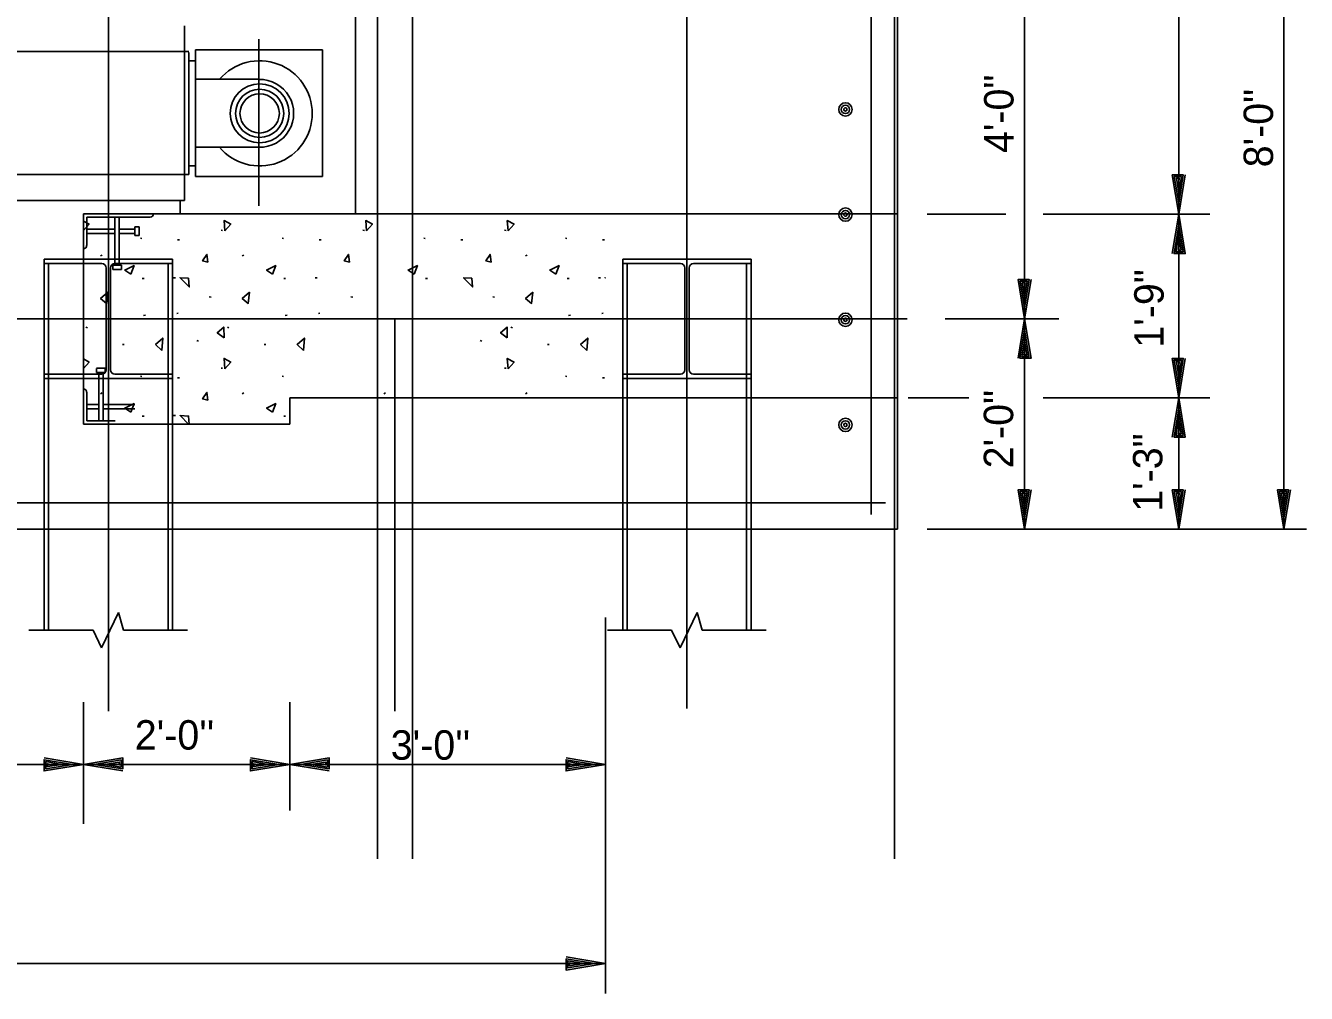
# Model space of a CAD drawing. Extents: x -11983 to -11903, y -13969.5 to -13913.5.
# Drawn here: x -11943.67 to -11931.5, y -13933.48 to -13924.28 of the extents above; entities that cross this region are included whole.
import ezdxf

# ---------------------------------------------------------------- set-up
doc = ezdxf.new("R2010")
doc.units = 0
for name, color, linetype in [('Level 1', 7, 'Continuous'), ('Level 2', 7, 'Continuous'), ('Level 22', 7, 'Continuous'), ('Level 25', 7, 'Continuous'), ('Level 3', 7, 'Continuous'), ('Level 44', 7, 'Continuous'), ('Level 50', 7, 'Continuous'), ('Level 6', 7, 'Continuous')]:
    doc.layers.add(name, color=color, linetype=linetype)

msp = doc.modelspace()

# ---------------------------------------------------------------- linework, layer by layer
at = {"layer": 'Level 1'}
msp.add_line((-11932.713, -13926.07), (-11932.713, -13927.816), dxfattribs=at)
at = {"layer": 'Level 2'}
for p, q in [((-11940.33, -13917.157), (-11940.33, -13932.202)), ((-11939.997, -13917.157), (-11939.997, -13932.202)), ((-11935.413, -13917.157), (-11935.413, -13932.202)), ((-11935.387, -13921.074), (-11935.387, -13927.066)), ((-11935.387, -13921.074), (-11935.387, -13929.066)), ((-11942.163, -13924.279), (-11942.163, -13925.941)), ((-11942.059, -13925.713), (-11942.059, -13924.506)), ((-11940.852, -13924.506), (-11942.059, -13924.506)), ((-11940.852, -13925.713), (-11940.852, -13924.506)), ((-11968.183, -13924.524), (-11942.122, -13924.524)), ((-11942.163, -13924.532), (-11942.163, -13925.698)), ((-11942.122, -13924.532), (-11942.122, -13925.691)), ((-11942.059, -13924.61), (-11942.122, -13924.61)), ((-11941.456, -13924.787), (-11942.059, -13924.787)), ((-11941.456, -13925.432), (-11942.059, -13925.432)), ((-11968.183, -13925.691), (-11942.122, -13925.691)), ((-11942.059, -13925.609), (-11942.122, -13925.609)), ((-11940.852, -13925.713), (-11942.059, -13925.713)), ((-11968.183, -13925.941), (-11942.163, -13925.941)), ((-11942.458, -13926.066), (-11943.125, -13926.066)), ((-11943.125, -13926.066), (-11943.125, -13926.399)), ((-11943.125, -13926.066), (-11943.125, -13928.066)), ((-11935.387, -13926.066), (-11943.125, -13926.066)), ((-11942.364, -13926.066), (-11943.125, -13926.066)), ((-11942.792, -13926.066), (-11942.792, -13926.066)), ((-11942.489, -13926.097), (-11943.093, -13926.097)), ((-11943.093, -13926.368), (-11943.093, -13926.097)), ((-11942.825, -13926.212), (-11943.093, -13926.212)), ((-11942.825, -13926.555), (-11942.825, -13926.097)), ((-11942.784, -13926.555), (-11942.784, -13926.097)), ((-11942.635, -13926.212), (-11942.784, -13926.212)), ((-11942.635, -13926.274), (-11942.635, -13926.191)), ((-11942.594, -13926.191), (-11942.635, -13926.191)), ((-11942.594, -13926.274), (-11942.594, -13926.191)), ((-11942.825, -13926.253), (-11943.093, -13926.253)), ((-11942.635, -13926.253), (-11942.784, -13926.253)), ((-11942.594, -13926.274), (-11942.635, -13926.274)), ((-11943.125, -13926.399), (-11943.125, -13926.399)), ((-11943.125, -13926.399), (-11943.125, -13927.733)), ((-11942.278, -13926.498), (-11943.497, -13926.498)), ((-11943.497, -13926.498), (-11943.497, -13926.54)), ((-11943.497, -13926.54), (-11943.497, -13928.566)), ((-11942.95, -13926.54), (-11943.497, -13926.54)), ((-11943.455, -13926.54), (-11943.455, -13928.566)), ((-11942.763, -13926.555), (-11942.846, -13926.555)), ((-11942.846, -13926.595), (-11942.846, -13926.555)), ((-11942.278, -13926.54), (-11942.825, -13926.54)), ((-11942.763, -13926.595), (-11942.763, -13926.555)), ((-11942.32, -13926.54), (-11942.32, -13928.566)), ((-11942.278, -13926.498), (-11942.278, -13926.54)), ((-11942.278, -13926.54), (-11942.278, -13928.566)), ((-11936.778, -13926.498), (-11937.997, -13926.498)), ((-11937.997, -13926.498), (-11937.997, -13926.54)), ((-11937.997, -13926.54), (-11937.997, -13928.566)), ((-11937.45, -13926.54), (-11937.997, -13926.54)), ((-11937.955, -13926.54), (-11937.955, -13928.566)), ((-11936.778, -13926.54), (-11937.325, -13926.54)), ((-11936.82, -13926.54), (-11936.82, -13928.566)), ((-11936.778, -13926.498), (-11936.778, -13926.54)), ((-11936.778, -13926.54), (-11936.778, -13928.566)), ((-11942.908, -13926.582), (-11942.908, -13927.55)), ((-11942.867, -13926.582), (-11942.867, -13927.55)), ((-11942.763, -13926.597), (-11942.846, -13926.597)), ((-11937.408, -13926.582), (-11937.408, -13927.55)), ((-11937.367, -13926.582), (-11937.367, -13927.55)), ((-11935.387, -13927.066), (-11935.387, -13929.066)), ((-11942.917, -13927.535), (-11943, -13927.535)), ((-11943, -13927.537), (-11943, -13927.577)), ((-11942.917, -13927.537), (-11942.917, -13927.577)), ((-11942.95, -13927.592), (-11943.497, -13927.592)), ((-11943.497, -13927.592), (-11943.497, -13927.634)), ((-11942.278, -13927.634), (-11943.497, -13927.634)), ((-11942.917, -13927.577), (-11943, -13927.577)), ((-11942.979, -13927.577), (-11942.979, -13928.035)), ((-11942.937, -13927.577), (-11942.937, -13928.035)), ((-11942.278, -13927.592), (-11942.825, -13927.592)), ((-11942.278, -13927.592), (-11942.278, -13927.634)), ((-11937.45, -13927.592), (-11937.997, -13927.592)), ((-11937.997, -13927.592), (-11937.997, -13927.634)), ((-11936.778, -13927.634), (-11937.997, -13927.634)), ((-11936.778, -13927.592), (-11937.325, -13927.592)), ((-11936.778, -13927.592), (-11936.778, -13927.634)), ((-11943.125, -13927.733), (-11943.125, -13927.733)), ((-11943.125, -13927.733), (-11943.125, -13928.066)), ((-11943.093, -13927.764), (-11943.093, -13928.035)), ((-11942.979, -13927.879), (-11943.093, -13927.879)), ((-11942.635, -13927.879), (-11942.937, -13927.879)), ((-11941.163, -13927.816), (-11941.163, -13928.066)), ((-11935.387, -13927.816), (-11941.163, -13927.816)), ((-11942.979, -13927.92), (-11943.093, -13927.92)), ((-11942.823, -13928.035), (-11943.093, -13928.035)), ((-11942.635, -13927.92), (-11942.937, -13927.92)), ((-11941.163, -13928.066), (-11943.125, -13928.066)), ((-11943.497, -13930.027), (-11943.497, -13928.566)), ((-11943.455, -13930.027), (-11943.455, -13928.566)), ((-11942.32, -13930.027), (-11942.32, -13928.566)), ((-11942.278, -13930.027), (-11942.278, -13928.566)), ((-11937.997, -13930.027), (-11937.997, -13928.566)), ((-11937.955, -13930.027), (-11937.955, -13928.566)), ((-11936.82, -13930.027), (-11936.82, -13928.566)), ((-11936.778, -13930.027), (-11936.778, -13928.566)), ((-11935.387, -13929.066), (-11957.178, -13929.066)), ((-11936.387, -13929.066), (-11936.662, -13929.066)), ((-11942.79, -13929.857), (-11942.953, -13930.194)), ((-11942.742, -13930.027), (-11942.79, -13929.857)), ((-11937.29, -13929.857), (-11937.453, -13930.194)), ((-11937.242, -13930.027), (-11937.29, -13929.857)), ((-11943.033, -13930.027), (-11943.643, -13930.027)), ((-11942.953, -13930.194), (-11943.033, -13930.027)), ((-11942.134, -13930.027), (-11942.742, -13930.027)), ((-11937.533, -13930.027), (-11938.143, -13930.027)), ((-11937.453, -13930.194), (-11937.533, -13930.027)), ((-11936.634, -13930.027), (-11937.242, -13930.027))]:
    msp.add_line(p, q, dxfattribs=at)
for radius in [0.281, 0.229, 0.187]:
    msp.add_circle((-11941.449, -13925.111), radius, dxfattribs=at)
for centre, radius, start, end in [((-11941.449, -13925.111), 0.5, 220.0641, 139.6289), ((-11941.449, -13925.111), 0.323, 268.7527, 91.2396), ((-11942.489, -13926.066), 0.0312, 270, 0), ((-11943.125, -13926.368), 0.0312, 270, 0), ((-11942.95, -13926.582), 0.0417, 0, 90), ((-11942.825, -13926.582), 0.0417, 90, 180), ((-11937.45, -13926.582), 0.0417, 0, 90), ((-11937.325, -13926.582), 0.0417, 90, 180), ((-11942.95, -13927.55), 0.0417, 270, 0), ((-11942.825, -13927.55), 0.0417, 180, 270), ((-11937.45, -13927.55), 0.0417, 270, 0), ((-11937.325, -13927.55), 0.0417, 180, 270), ((-11943.125, -13927.764), 0.0312, 0, 90)]:
    msp.add_arc(centre, radius, start, end, dxfattribs=at)
at = {"layer": 'Level 22'}
for p, q in [((-11942.887, -13924.649), (-11942.887, -13923.074)), ((-11937.387, -13924.649), (-11937.387, -13923.074)), ((-11942.887, -13924.649), (-11942.887, -13927.066)), ((-11942.887, -13924.649), (-11942.887, -13927.066)), ((-11937.387, -13924.649), (-11937.387, -13927.066)), ((-11942.887, -13927.066), (-11942.887, -13927.857)), ((-11937.387, -13927.066), (-11937.387, -13927.857)), ((-11943.125, -13930.71), (-11943.125, -13931.868)), ((-11941.163, -13930.71), (-11941.163, -13931.742)), ((-11938.163, -13931.302), (-11938.163, -13930.71)), ((-11941.163, -13931.302), (-11943.125, -13931.302)), ((-11938.163, -13931.302), (-11941.163, -13931.302))]:
    msp.add_line(p, q, dxfattribs=at)
at = {"layer": 'Level 25'}
for p, q in [((-11940.538, -13926.066), (-11940.538, -13923.849)), ((-11942.205, -13926.066), (-11942.205, -13925.941))]:
    msp.add_line(p, q, dxfattribs=at)
at = {"layer": 'Level 3'}
for p, q in [((-11932.713, -13921.074), (-11932.713, -13926.07)), ((-11931.713, -13921.074), (-11931.713, -13929.066)), ((-11934.178, -13923.074), (-11934.178, -13927.066)), ((-11932.713, -13925.966), (-11932.713, -13925.966)), ((-11934.355, -13926.07), (-11935.104, -13926.07)), ((-11932.418, -13926.07), (-11934.002, -13926.07)), ((-11932.713, -13926.07), (-11932.713, -13926.07)), ((-11935.294, -13927.066), (-11955.163, -13927.066)), ((-11942.887, -13927.066), (-11942.887, -13930.796)), ((-11942.887, -13927.066), (-11942.887, -13930.77)), ((-11940.163, -13927.066), (-11940.163, -13930.796)), ((-11940.163, -13927.066), (-11940.163, -13930.796)), ((-11937.387, -13927.066), (-11937.387, -13930.77)), ((-11933.851, -13927.066), (-11934.934, -13927.066)), ((-11934.178, -13927.066), (-11934.178, -13929.066)), ((-11934.707, -13927.816), (-11935.286, -13927.816)), ((-11932.418, -13927.816), (-11934.002, -13927.816)), ((-11932.713, -13927.816), (-11932.713, -13929.066)), ((-11931.713, -13928.962), (-11931.713, -13928.962)), ((-11931.499, -13929.066), (-11935.104, -13929.066)), ((-11931.713, -13929.066), (-11931.713, -13929.066)), ((-11938.163, -13929.904), (-11938.163, -13932.694)), ((-11938.163, -13930.824), (-11938.163, -13933.48)), ((-11967.163, -13931.302), (-11943.125, -13931.302)), ((-11938.163, -13933.196), (-11972.163, -13933.196))]:
    msp.add_line(p, q, dxfattribs=at)
for points in [[(-11932.651, -13925.696), (-11932.713, -13926.07), (-11932.775, -13925.696), (-11932.669, -13925.696), (-11932.713, -13925.966), (-11932.755, -13925.712), (-11932.687, -13925.712), (-11932.713, -13925.866), (-11932.735, -13925.728), (-11932.707, -13925.728), (-11932.713, -13925.762)], [(-11931.651, -13928.692), (-11931.713, -13929.066), (-11931.775, -13928.692), (-11931.669, -13928.692), (-11931.713, -13928.962), (-11931.755, -13928.708), (-11931.687, -13928.708), (-11931.713, -13928.862), (-11931.735, -13928.724), (-11931.707, -13928.724), (-11931.713, -13928.758)]]:
    msp.add_lwpolyline(points, dxfattribs=at)
at = {"layer": 'Level 44'}
for p, q in [((-11942.57, -13926.302), (-11942.583, -13926.299)), ((-11942.211, -13926.313), (-11942.229, -13926.313)), ((-11941.801, -13926.224), (-11941.814, -13926.223)), ((-11941.223, -13926.302), (-11941.236, -13926.299)), ((-11940.864, -13926.313), (-11940.882, -13926.313)), ((-11940.454, -13926.224), (-11940.467, -13926.223)), ((-11939.876, -13926.302), (-11939.89, -13926.299)), ((-11939.518, -13926.313), (-11939.536, -13926.313)), ((-11939.107, -13926.224), (-11939.121, -13926.223)), ((-11938.53, -13926.302), (-11938.543, -13926.299)), ((-11938.171, -13926.313), (-11938.189, -13926.313)), ((-11942.947, -13926.459), (-11942.963, -13926.467)), ((-11941.6, -13926.459), (-11941.616, -13926.467)), ((-11938.907, -13926.459), (-11938.923, -13926.467)), ((-11942.548, -13926.68), (-11942.566, -13926.68)), ((-11942.25, -13926.674), (-11942.267, -13926.674)), ((-11941.202, -13926.68), (-11941.22, -13926.68)), ((-11940.903, -13926.674), (-11940.92, -13926.674)), ((-11939.855, -13926.68), (-11939.873, -13926.68)), ((-11938.508, -13926.68), (-11938.526, -13926.68)), ((-11938.21, -13926.674), (-11938.227, -13926.674)), ((-11941.91, -13926.86), (-11941.928, -13926.857)), ((-11940.564, -13926.86), (-11940.581, -13926.857)), ((-11939.217, -13926.86), (-11939.234, -13926.857)), ((-11942.534, -13927.029), (-11942.552, -13927.034)), ((-11942.223, -13927.011), (-11942.236, -13927.016)), ((-11941.187, -13927.029), (-11941.205, -13927.034)), ((-11940.877, -13927.011), (-11940.89, -13927.016)), ((-11938.494, -13927.029), (-11938.512, -13927.034)), ((-11938.183, -13927.011), (-11938.196, -13927.016)), ((-11943.087, -13927.152), (-11943.102, -13927.143)), ((-11941.741, -13927.152), (-11941.756, -13927.143)), ((-11939.047, -13927.152), (-11939.062, -13927.143)), ((-11942.738, -13927.308), (-11942.753, -13927.31)), ((-11942.031, -13927.276), (-11942.045, -13927.27)), ((-11941.391, -13927.308), (-11941.406, -13927.31)), ((-11939.338, -13927.276), (-11939.352, -13927.27)), ((-11938.698, -13927.308), (-11938.713, -13927.31)), ((-11941.801, -13927.535), (-11941.814, -13927.534)), ((-11939.107, -13927.535), (-11939.121, -13927.534)), ((-11942.57, -13927.613), (-11942.583, -13927.611)), ((-11942.211, -13927.625), (-11942.229, -13927.625)), ((-11941.223, -13927.613), (-11941.236, -13927.611)), ((-11938.53, -13927.613), (-11938.543, -13927.611)), ((-11938.171, -13927.625), (-11938.189, -13927.625)), ((-11942.947, -13927.77), (-11942.963, -13927.778)), ((-11941.6, -13927.77), (-11941.616, -13927.778)), ((-11940.254, -13927.77), (-11940.27, -13927.778)), ((-11938.907, -13927.77), (-11938.923, -13927.778)), ((-11942.548, -13927.992), (-11942.566, -13927.992)), ((-11942.25, -13927.985), (-11942.267, -13927.985)), ((-11941.202, -13927.992), (-11941.22, -13927.992))]:
    msp.add_line(p, q, dxfattribs=at)
for points in [[(-11943.125, -13926.225), (-11943.071, -13926.164), (-11943.125, -13926.136)], [(-11938.163, -13926.674), (-11938.165, -13926.674), (-11938.163, -13926.675)], [(-11943.125, -13927.537), (-11943.071, -13927.476), (-11943.125, -13927.447)], [(-11942.119, -13928.066), (-11942.125, -13927.99), (-11942.205, -13927.985), (-11942.126, -13928.066)]]:
    msp.add_lwpolyline(points, dxfattribs=at)
for points in [[(-11941.781, -13926.228), (-11941.724, -13926.164), (-11941.788, -13926.13)], [(-11940.435, -13926.228), (-11940.378, -13926.164), (-11940.441, -13926.13)], [(-11939.088, -13926.228), (-11939.031, -13926.164), (-11939.095, -13926.13)], [(-11941.942, -13926.526), (-11941.951, -13926.453), (-11941.992, -13926.514)], [(-11940.595, -13926.526), (-11940.604, -13926.453), (-11940.645, -13926.514)], [(-11939.248, -13926.526), (-11939.258, -13926.453), (-11939.299, -13926.514)], [(-11942.674, -13926.641), (-11942.643, -13926.559), (-11942.731, -13926.602)], [(-11941.328, -13926.641), (-11941.296, -13926.559), (-11941.384, -13926.602)], [(-11939.981, -13926.641), (-11939.949, -13926.559), (-11940.038, -13926.602)], [(-11938.634, -13926.641), (-11938.603, -13926.559), (-11938.691, -13926.602)], [(-11942.125, -13926.678), (-11942.205, -13926.674), (-11942.118, -13926.762)], [(-11939.431, -13926.678), (-11939.511, -13926.674), (-11939.425, -13926.762)], [(-11942.893, -13926.812), (-11942.961, -13926.872), (-11942.905, -13926.919)], [(-11941.546, -13926.812), (-11941.615, -13926.872), (-11941.558, -13926.919)], [(-11938.853, -13926.812), (-11938.921, -13926.872), (-11938.865, -13926.919)], [(-11941.788, -13927.247), (-11941.852, -13927.198), (-11941.791, -13927.144)], [(-11939.095, -13927.247), (-11939.159, -13927.198), (-11939.097, -13927.144)], [(-11942.378, -13927.367), (-11942.439, -13927.31), (-11942.371, -13927.249)], [(-11941.031, -13927.367), (-11941.093, -13927.31), (-11941.024, -13927.249)], [(-11938.338, -13927.367), (-11938.399, -13927.31), (-11938.331, -13927.249)], [(-11941.781, -13927.54), (-11941.724, -13927.476), (-11941.788, -13927.442)], [(-11939.088, -13927.54), (-11939.031, -13927.476), (-11939.095, -13927.442)], [(-11941.942, -13927.838), (-11941.951, -13927.765), (-11941.992, -13927.826)], [(-11942.674, -13927.953), (-11942.643, -13927.871), (-11942.731, -13927.914)], [(-11941.328, -13927.953), (-11941.296, -13927.871), (-11941.384, -13927.914)]]:
    msp.add_lwpolyline(points, close=True, dxfattribs=at)
at = {"layer": 'Level 50'}
for p, q in [((-11941.456, -13924.407), (-11941.456, -13925.991)), ((-11932.713, -13926.07), (-11932.713, -13926.07)), ((-11932.713, -13926.174), (-11932.713, -13926.174)), ((-11934.178, -13926.962), (-11934.178, -13926.962)), ((-11934.178, -13927.066), (-11934.178, -13927.066)), ((-11934.178, -13927.066), (-11934.178, -13927.066)), ((-11934.178, -13927.17), (-11934.178, -13927.17)), ((-11932.713, -13927.712), (-11932.713, -13927.712)), ((-11932.713, -13927.816), (-11932.713, -13927.816)), ((-11932.713, -13927.816), (-11932.713, -13927.816)), ((-11932.713, -13927.92), (-11932.713, -13927.92)), ((-11943.125, -13928.066), (-11942.792, -13928.066)), ((-11934.178, -13928.962), (-11934.178, -13928.962)), ((-11932.713, -13928.962), (-11932.713, -13928.962)), ((-11934.178, -13929.066), (-11934.178, -13929.066)), ((-11932.713, -13929.066), (-11932.713, -13929.066)), ((-11943.229, -13931.302), (-11943.229, -13931.302)), ((-11943.125, -13931.302), (-11943.125, -13931.302)), ((-11943.125, -13931.302), (-11943.125, -13931.302)), ((-11943.021, -13931.302), (-11943.021, -13931.302)), ((-11941.267, -13931.302), (-11941.267, -13931.302)), ((-11941.163, -13931.302), (-11941.163, -13931.302)), ((-11941.163, -13931.302), (-11941.163, -13931.302)), ((-11941.059, -13931.302), (-11941.059, -13931.302)), ((-11938.267, -13931.302), (-11938.267, -13931.302)), ((-11938.163, -13931.302), (-11938.163, -13931.302)), ((-11938.267, -13933.196), (-11938.267, -13933.196)), ((-11938.163, -13933.196), (-11938.163, -13933.196))]:
    msp.add_line(p, q, dxfattribs=at)
for points in [[(-11932.775, -13926.444), (-11932.713, -13926.07), (-11932.651, -13926.444), (-11932.757, -13926.444), (-11932.713, -13926.174), (-11932.671, -13926.428), (-11932.739, -13926.428), (-11932.713, -13926.274), (-11932.691, -13926.412), (-11932.719, -13926.412), (-11932.713, -13926.378)], [(-11934.116, -13926.692), (-11934.178, -13927.066), (-11934.24, -13926.692), (-11934.134, -13926.692), (-11934.178, -13926.962), (-11934.22, -13926.708), (-11934.152, -13926.708), (-11934.178, -13926.862), (-11934.2, -13926.724), (-11934.172, -13926.724), (-11934.178, -13926.758)], [(-11934.24, -13927.44), (-11934.178, -13927.066), (-11934.116, -13927.44), (-11934.222, -13927.44), (-11934.178, -13927.17), (-11934.136, -13927.424), (-11934.204, -13927.424), (-11934.178, -13927.27), (-11934.156, -13927.408), (-11934.184, -13927.408), (-11934.178, -13927.374)], [(-11932.651, -13927.442), (-11932.713, -13927.816), (-11932.775, -13927.442), (-11932.669, -13927.442), (-11932.713, -13927.712), (-11932.755, -13927.458), (-11932.687, -13927.458), (-11932.713, -13927.612), (-11932.735, -13927.474), (-11932.707, -13927.474), (-11932.713, -13927.508)], [(-11932.775, -13928.19), (-11932.713, -13927.816), (-11932.651, -13928.19), (-11932.757, -13928.19), (-11932.713, -13927.92), (-11932.671, -13928.174), (-11932.739, -13928.174), (-11932.713, -13928.02), (-11932.691, -13928.158), (-11932.719, -13928.158), (-11932.713, -13928.124)], [(-11934.116, -13928.692), (-11934.178, -13929.066), (-11934.24, -13928.692), (-11934.134, -13928.692), (-11934.178, -13928.962), (-11934.22, -13928.708), (-11934.152, -13928.708), (-11934.178, -13928.862), (-11934.2, -13928.724), (-11934.172, -13928.724), (-11934.178, -13928.758)], [(-11932.651, -13928.692), (-11932.713, -13929.066), (-11932.775, -13928.692), (-11932.669, -13928.692), (-11932.713, -13928.962), (-11932.755, -13928.708), (-11932.687, -13928.708), (-11932.713, -13928.862), (-11932.735, -13928.724), (-11932.707, -13928.724), (-11932.713, -13928.758)], [(-11943.499, -13931.24), (-11943.125, -13931.302), (-11943.499, -13931.364), (-11943.499, -13931.258), (-11943.229, -13931.302), (-11943.483, -13931.344), (-11943.483, -13931.276), (-11943.329, -13931.302), (-11943.467, -13931.324), (-11943.467, -13931.296), (-11943.433, -13931.302)], [(-11942.751, -13931.364), (-11943.125, -13931.302), (-11942.751, -13931.24), (-11942.751, -13931.346), (-11943.021, -13931.302), (-11942.767, -13931.26), (-11942.767, -13931.328), (-11942.921, -13931.302), (-11942.783, -13931.28), (-11942.783, -13931.308), (-11942.817, -13931.302)], [(-11941.537, -13931.24), (-11941.163, -13931.302), (-11941.537, -13931.364), (-11941.537, -13931.258), (-11941.267, -13931.302), (-11941.521, -13931.344), (-11941.521, -13931.276), (-11941.367, -13931.302), (-11941.505, -13931.324), (-11941.505, -13931.296), (-11941.471, -13931.302)], [(-11940.789, -13931.364), (-11941.163, -13931.302), (-11940.789, -13931.24), (-11940.789, -13931.346), (-11941.059, -13931.302), (-11940.805, -13931.26), (-11940.805, -13931.328), (-11940.959, -13931.302), (-11940.821, -13931.28), (-11940.821, -13931.308), (-11940.855, -13931.302)], [(-11938.537, -13931.24), (-11938.163, -13931.302), (-11938.537, -13931.364), (-11938.537, -13931.258), (-11938.267, -13931.302), (-11938.521, -13931.344), (-11938.521, -13931.276), (-11938.367, -13931.302), (-11938.505, -13931.324), (-11938.505, -13931.296), (-11938.471, -13931.302)], [(-11938.537, -13933.134), (-11938.163, -13933.196), (-11938.537, -13933.258), (-11938.537, -13933.152), (-11938.267, -13933.196), (-11938.521, -13933.238), (-11938.521, -13933.17), (-11938.367, -13933.196), (-11938.505, -13933.218), (-11938.505, -13933.19), (-11938.471, -13933.196)]]:
    msp.add_lwpolyline(points, dxfattribs=at)
at = {"layer": 'Level 6'}
for p, q in [((-11935.637, -13921.193), (-11935.637, -13928.927)), ((-11935.499, -13928.816), (-11957.178, -13928.816))]:
    msp.add_line(p, q, dxfattribs=at)
for centre, radius in [((-11935.881, -13925.074), 0.0633), ((-11935.881, -13925.074), 0.0396), ((-11935.881, -13925.074), 0.0158), ((-11935.881, -13926.074), 0.0633), ((-11935.881, -13926.074), 0.0396), ((-11935.881, -13926.074), 0.0158), ((-11935.881, -13927.074), 0.0633), ((-11935.881, -13927.074), 0.0396), ((-11935.881, -13927.074), 0.0158), ((-11935.881, -13928.074), 0.0633), ((-11935.881, -13928.074), 0.0396), ((-11935.881, -13928.074), 0.0158)]:
    msp.add_circle(centre, radius, dxfattribs=at)

# ---------------------------------------------------------------- texts
at = {"layer": 'Level 3'}
for s, p in [('4\'-0"', (-11934.283, -13925.488)), ('8\'-0"', (-11931.816, -13925.624)), ('1\'-9"', (-11932.856, -13927.339)), ('2\'-0"', (-11934.286, -13928.487)), ('1\'-3"', (-11932.868, -13928.9))]:
    msp.add_text(s, height=0.28, rotation=90, dxfattribs=at).set_placement(p)
for s, p in [("2'-0'' ", (-11942.636, -13931.162)), ("3'-0'' ", (-11940.203, -13931.258))]:
    msp.add_text(s, height=0.28, dxfattribs=at).set_placement(p)

doc.saveas('drawing.dxf')
